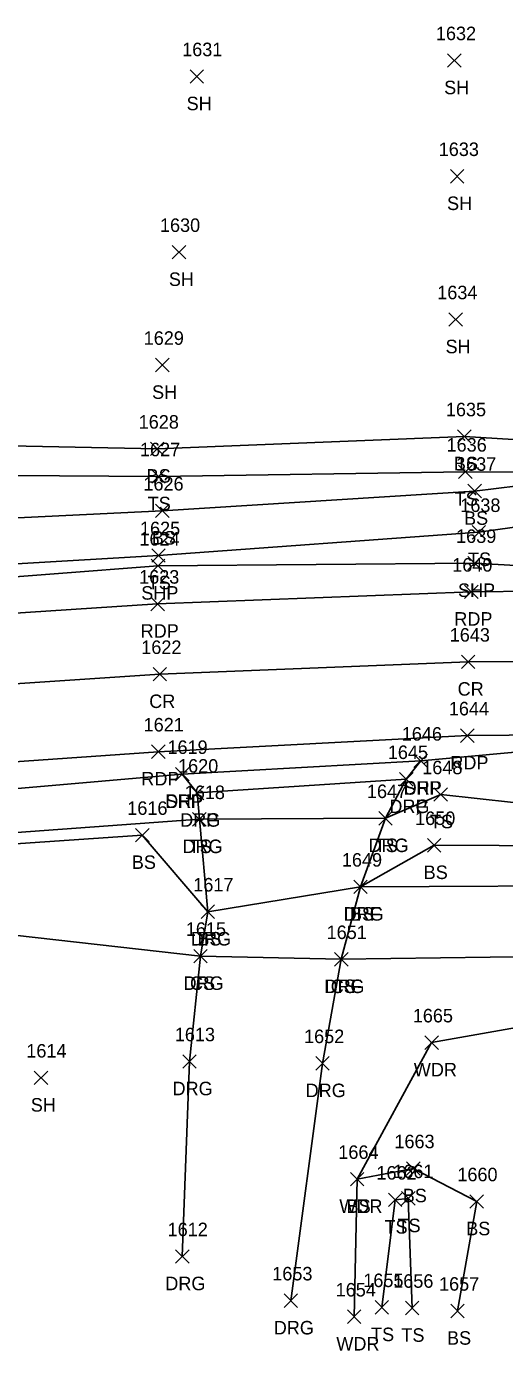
# Model space of a CAD drawing. Extents: x 1497084 to 1499861, y 734741 to 735567.
# Drawn here: x 1499358.9 to 1499429.7, y 735363.4 to 735559.4 of the extents above; entities that cross this region are included whole.
import ezdxf

# ---------------------------------------------------------------- set-up
doc = ezdxf.new("R2010")
doc.units = 0
for name, color, linetype in [('L_A', 7, 'Continuous'), ('L_I', 7, 'Continuous'), ('L_TIC', 7, 'Continuous'), ('LAWA', 7, 'Continuous'), ('LELB', 7, 'Continuous'), ('P_A', 7, 'Continuous'), ('P_I', 7, 'Continuous'), ('P_TIC', 7, 'Continuous'), ('PET', 7, 'Continuous'), ('PRC', 7, 'Continuous'), ('PSP', 7, 'Continuous'), ('R_A', 7, 'Continuous'), ('R_I', 7, 'Continuous'), ('R_TIC', 7, 'Continuous'), ('RDF', 7, 'Continuous'), ('RDG', 7, 'Continuous'), ('RDP', 7, 'Continuous')]:
    doc.layers.add(name, color=color, linetype=linetype)

msp = doc.modelspace()

# ---------------------------------------------------------------- linework, layer by layer
at = {"layer": 'L_TIC'}
for points in [[(1499421.24, 735553.38), (1499423.24, 735555.38)], [(1499423.24, 735553.38), (1499421.24, 735555.38)], [(1499383.1, 735551.01), (1499385.1, 735553.01)], [(1499385.1, 735551.01), (1499383.1, 735553.01)], [(1499421.66, 735536.23), (1499423.66, 735538.23)], [(1499423.66, 735536.23), (1499421.66, 735538.23)], [(1499380.47, 735524.99), (1499382.47, 735526.99)], [(1499382.47, 735524.99), (1499380.47, 735526.99)], [(1499421.44, 735515.03), (1499423.44, 735517.03)], [(1499423.44, 735515.03), (1499421.44, 735517.03)], [(1499377.98, 735508.28), (1499379.98, 735510.28)], [(1499379.98, 735508.28), (1499377.98, 735510.28)], [(1499422.72, 735497.7), (1499424.72, 735499.7)], [(1499424.72, 735497.7), (1499422.72, 735499.7)], [(1499377.23, 735495.87), (1499379.23, 735497.87)], [(1499379.23, 735495.87), (1499377.23, 735497.87)], [(1499377.42, 735491.78), (1499379.42, 735493.78)], [(1499379.42, 735491.78), (1499377.42, 735493.78)], [(1499422.87, 735492.47), (1499424.87, 735494.47)], [(1499424.87, 735492.47), (1499422.87, 735494.47)], [(1499424.23, 735489.63), (1499426.23, 735491.63)], [(1499426.23, 735489.63), (1499424.23, 735491.63)], [(1499377.98, 735486.71), (1499379.98, 735488.71)], [(1499379.98, 735486.71), (1499377.98, 735488.71)], [(1499424.85, 735483.53), (1499426.85, 735485.53)], [(1499426.85, 735483.53), (1499424.85, 735485.53)], [(1499377.42, 735480.09), (1499379.42, 735482.09)], [(1499379.42, 735480.09), (1499377.42, 735482.09)], [(1499419.22, 735444.71), (1499421.22, 735446.71)], [(1499421.22, 735444.71), (1499419.22, 735446.71)], [(1499383.48, 735441.03), (1499385.48, 735443.03)], [(1499385.48, 735441.03), (1499383.48, 735443.03)], [(1499411.03, 735441.18), (1499413.03, 735443.18)], [(1499413.03, 735441.18), (1499411.03, 735443.18)], [(1499375.02, 735438.69), (1499377.02, 735440.69)], [(1499377.02, 735438.69), (1499375.02, 735440.69)], [(1499418.24, 735437.19), (1499420.24, 735439.19)], [(1499420.24, 735437.19), (1499418.24, 735439.19)], [(1499407.33, 735431.03), (1499409.33, 735433.03)], [(1499409.33, 735431.03), (1499407.33, 735433.03)], [(1499384.74, 735427.35), (1499386.74, 735429.35)], [(1499386.74, 735427.35), (1499384.74, 735429.35)], [(1499383.64, 735420.78), (1499385.64, 735422.78)], [(1499385.64, 735420.78), (1499383.64, 735422.78)], [(1499404.49, 735420.31), (1499406.49, 735422.31)], [(1499406.49, 735420.31), (1499404.49, 735422.31)], [(1499417.87, 735407.97), (1499419.87, 735409.97)], [(1499419.87, 735407.97), (1499417.87, 735409.97)], [(1499360.03, 735402.76), (1499362.03, 735404.76)], [(1499362.03, 735402.76), (1499360.03, 735404.76)], [(1499415.15, 735389.34), (1499417.15, 735391.34)], [(1499417.15, 735389.34), (1499415.15, 735391.34)], [(1499406.84, 735387.76), (1499408.84, 735389.76)], [(1499408.84, 735387.76), (1499406.84, 735389.76)], [(1499406.84, 735387.76), (1499408.84, 735389.76)], [(1499408.84, 735387.76), (1499406.84, 735389.76)], [(1499412.48, 735384.7), (1499414.48, 735386.7)], [(1499414.48, 735384.7), (1499412.48, 735386.7)], [(1499412.48, 735384.7), (1499414.48, 735386.7)], [(1499414.48, 735384.7), (1499412.48, 735386.7)], [(1499414.41, 735384.91), (1499416.41, 735386.91)], [(1499416.41, 735384.91), (1499414.41, 735386.91)], [(1499424.55, 735384.45), (1499426.55, 735386.45)], [(1499426.55, 735384.45), (1499424.55, 735386.45)], [(1499410.49, 735368.78), (1499412.49, 735370.78)], [(1499412.49, 735368.78), (1499410.49, 735370.78)], [(1499414.98, 735368.68), (1499416.98, 735370.68)], [(1499416.98, 735368.68), (1499414.98, 735370.68)], [(1499421.71, 735368.25), (1499423.71, 735370.25)], [(1499423.71, 735368.25), (1499421.71, 735370.25)], [(1499406.4, 735367.39), (1499408.4, 735369.39)], [(1499408.4, 735367.39), (1499406.4, 735369.39)]]:
    msp.add_lwpolyline(points, dxfattribs=at)
at = {"layer": 'LAWA'}
msp.add_lwpolyline([(1499407.4, 735368.39), (1499407.84, 735388.76), (1499418.87, 735408.97), (1499449.6, 735414.41), (1499467.22, 735411), (1499485.54, 735404.01), (1499495.84, 735403.46), (1499517.61, 735404.27)], dxfattribs=at)
at = {"layer": 'LELB'}
for points in [[(1498873.92, 735413.56), (1498885.61, 735419.45), (1498937.6, 735431.47), (1498992.42, 735446.17), (1499046.55, 735456.42), (1499100.05, 735466.4), (1499155.3, 735475.02), (1499211.81, 735485.81), (1499272.89, 735498.35), (1499312.63, 735498.22), (1499378.23, 735496.87), (1499423.72, 735498.7), (1499448.77, 735497.16), (1499468.03, 735503.5), (1499479.61, 735506.38), (1499485.8, 735535.79), (1499495.73, 735555.05)], [(1498887.06, 735413.08), (1498886.64, 735416.64), (1498937.22, 735426.43), (1498992.82, 735439.97), (1499047, 735450.43), (1499100.75, 735458.28), (1499155.76, 735466.18), (1499214.75, 735478.18), (1499272.85, 735494.27), (1499312.36, 735493.24), (1499378.42, 735492.78), (1499423.87, 735493.47), (1499447.7, 735493.36), (1499467.98, 735499.39), (1499480.88, 735502.15), (1499491.75, 735532.72), (1499501.47, 735549.91)], [(1499315.72, 735484.63), (1499378.98, 735487.71), (1499425.23, 735490.63), (1499447.7, 735493.36), (1499468.5, 735489.63), (1499492.74, 735487.59), (1499503.65, 735483.67), (1499512.79, 735485.66), (1499516.41, 735481.94), (1499515.9, 735479.25)], [(1498836.02, 735409.82), (1498851.62, 735410.69), (1498873.71, 735408.53), (1498887.41, 735411.13), (1498937.88, 735419.58), (1498994.04, 735428.91), (1499054.48, 735438.88), (1499102.91, 735446.6), (1499157.52, 735455.49), (1499217.09, 735464.03), (1499265.79, 735469.16), (1499273.78, 735473.78), (1499316.12, 735477.44), (1499378.42, 735481.09), (1499425.85, 735484.53), (1499445.24, 735487.28), (1499459.87, 735483.77), (1499494.5, 735481.39), (1499511.88, 735480.66), (1499514.4, 735477.39)], [(1498902.07, 735368.05), (1498907.17, 735371.51), (1498940.32, 735377.55), (1498999.63, 735387.02), (1499017.69, 735389.23), (1499022.6, 735383.12), (1499048.5, 735392.29), (1499056.36, 735395.92), (1499109.05, 735409.57), (1499159.67, 735419.26), (1499225.84, 735428.89), (1499272.31, 735428.88), (1499323.36, 735436.06), (1499376.02, 735439.69), (1499385.74, 735428.35), (1499408.33, 735432.03), (1499419.24, 735438.19), (1499448.18, 735438.04), (1499493.15, 735436.77), (1499505.9, 735439.37), (1499516.74, 735441.77), (1499516.38, 735446.4), (1499513.83, 735450.64)], [(1499224.87, 735431.1), (1499271.08, 735434.05), (1499322.87, 735437.57), (1499384.48, 735442.03), (1499412.03, 735442.18), (1499420.22, 735445.71), (1499447.12, 735442.74), (1499493.29, 735444.7), (1499504.12, 735447.13), (1499512.27, 735451.02)], [(1499047.27, 735383.52), (1499066.78, 735390.4), (1499110.69, 735404.23), (1499164.91, 735411.78), (1499229.89, 735424.14), (1499272.31, 735428.88), (1499323.85, 735428.64), (1499384.64, 735421.78), (1499405.49, 735421.31)], [(1499422.71, 735369.25), (1499425.55, 735385.45), (1499416.15, 735390.34), (1499407.84, 735388.76)], [(1499411.49, 735369.78), (1499413.48, 735385.7)], [(1499415.98, 735369.68), (1499415.41, 735385.91), (1499413.48, 735385.7)]]:
    msp.add_lwpolyline(points, dxfattribs=at)
at = {"layer": 'P_TIC'}
for points in [[(1499377.34, 735478.55), (1499379.34, 735480.55)], [(1499379.34, 735478.55), (1499377.34, 735480.55)], [(1499424.23, 735478.95), (1499426.23, 735480.95)], [(1499426.23, 735478.95), (1499424.23, 735480.95)], [(1499423.75, 735474.7), (1499425.75, 735476.7)], [(1499425.75, 735474.7), (1499423.75, 735476.7)], [(1499377.29, 735472.92), (1499379.29, 735474.92)], [(1499379.29, 735472.92), (1499377.29, 735474.92)], [(1499423.29, 735464.34), (1499425.29, 735466.34)], [(1499425.29, 735464.34), (1499423.29, 735466.34)], [(1499377.61, 735462.51), (1499379.61, 735464.51)], [(1499379.61, 735462.51), (1499377.61, 735464.51)], [(1499423.16, 735453.42), (1499425.16, 735455.42)], [(1499425.16, 735453.42), (1499423.16, 735455.42)], [(1499377.39, 735451.04), (1499379.39, 735453.04)], [(1499379.39, 735451.04), (1499377.39, 735453.04)], [(1499416.25, 735449.68), (1499418.25, 735451.68)], [(1499418.25, 735449.68), (1499416.25, 735451.68)], [(1499380.94, 735447.71), (1499382.94, 735449.71)], [(1499382.94, 735447.71), (1499380.94, 735449.71)]]:
    msp.add_lwpolyline(points, dxfattribs=at)
at = {"layer": 'PET'}
for points in [[(1498838.32, 735395.91), (1498888.99, 735404.3), (1498938.22, 735411.59), (1498994.69, 735421.68), (1499054.78, 735430.96), (1499104.38, 735439.6), (1499157.66, 735447.8), (1499219.31, 735457.47), (1499265.92, 735463.89), (1499317.31, 735469.95), (1499378.29, 735473.92), (1499424.75, 735475.7), (1499462.5, 735476.09), (1499495.09, 735475.96), (1499513.91, 735475.18)], [(1498842.44, 735373.21), (1498892.67, 735381.87), (1498940.26, 735389.17), (1498997.67, 735398.94), (1499056.44, 735408.41), (1499108.2, 735417.59), (1499160.18, 735425.34), (1499224.61, 735435.78), (1499269.11, 735441.52), (1499319.5, 735447.91), (1499378.39, 735452.04), (1499424.16, 735454.42), (1499461.26, 735454.74), (1499493.51, 735454.63), (1499512.44, 735453.4), (1499513.2, 735464.25), (1499513.91, 735475.18)]]:
    msp.add_lwpolyline(points, dxfattribs=at)
at = {"layer": 'PRC'}
msp.add_lwpolyline([(1498839.89, 735384.37), (1498890.74, 735392.79), (1498939.31, 735400.24), (1498995.85, 735410.01), (1499056.08, 735419.64), (1499106.34, 735428.63), (1499159.02, 735436.58), (1499221.74, 735447.44), (1499267.15, 735453.23), (1499318.55, 735459.5), (1499378.61, 735463.51), (1499424.29, 735465.34), (1499461.73, 735465.4), (1499494.05, 735465.28), (1499513.2, 735464.25)], dxfattribs=at)
at = {"layer": 'PSP'}
for points in [[(1498833.8, 735399.85), (1498855.6, 735403.69), (1498873.7, 735405.84), (1498888.17, 735408.98), (1498937.73, 735416.37), (1498993.87, 735425.67), (1499054.79, 735435.66), (1499103.37, 735443.86), (1499157.46, 735452.91), (1499218.03, 735462.22), (1499265.79, 735469.16), (1499316.87, 735474.83), (1499378.34, 735479.55), (1499425.23, 735479.95), (1499462.88, 735477.81), (1499495.09, 735475.96)], [(1498843.61, 735368.57), (1498860.46, 735371.23), (1498865.28, 735372.42), (1498905.37, 735378.8), (1498940.19, 735384.06), (1498998.48, 735394.31), (1499018.85, 735397.58), (1499054.41, 735403.83), (1499108.72, 735412.03), (1499160.14, 735420.81), (1499224.87, 735431.1), (1499270.68, 735437.25), (1499320.13, 735443.34), (1499381.94, 735448.71), (1499417.25, 735450.68), (1499461.26, 735454.74)]]:
    msp.add_lwpolyline(points, dxfattribs=at)
at = {"layer": 'R_TIC'}
for points in [[(1499416.25, 735449.68), (1499418.25, 735451.68)], [(1499418.25, 735449.68), (1499416.25, 735451.68)], [(1499380.94, 735447.71), (1499382.94, 735449.71)], [(1499382.94, 735447.71), (1499380.94, 735449.71)], [(1499414.12, 735446.96), (1499416.12, 735448.96)], [(1499416.12, 735446.96), (1499414.12, 735448.96)], [(1499414.12, 735446.96), (1499416.12, 735448.96)], [(1499416.12, 735446.96), (1499414.12, 735448.96)], [(1499383.15, 735444.94), (1499385.15, 735446.94)], [(1499385.15, 735444.94), (1499383.15, 735446.94)], [(1499383.15, 735444.94), (1499385.15, 735446.94)], [(1499385.15, 735444.94), (1499383.15, 735446.94)], [(1499383.48, 735441.03), (1499385.48, 735443.03)], [(1499385.48, 735441.03), (1499383.48, 735443.03)], [(1499411.03, 735441.18), (1499413.03, 735443.18)], [(1499413.03, 735441.18), (1499411.03, 735443.18)], [(1499407.33, 735431.03), (1499409.33, 735433.03)], [(1499409.33, 735431.03), (1499407.33, 735433.03)], [(1499407.33, 735431.03), (1499409.33, 735433.03)], [(1499409.33, 735431.03), (1499407.33, 735433.03)], [(1499384.74, 735427.35), (1499386.74, 735429.35)], [(1499386.74, 735427.35), (1499384.74, 735429.35)], [(1499383.64, 735420.78), (1499385.64, 735422.78)], [(1499385.64, 735420.78), (1499383.64, 735422.78)], [(1499404.49, 735420.31), (1499406.49, 735422.31)], [(1499406.49, 735420.31), (1499404.49, 735422.31)], [(1499404.49, 735420.31), (1499406.49, 735422.31)], [(1499406.49, 735420.31), (1499404.49, 735422.31)], [(1499382.01, 735405.18), (1499384.01, 735407.18)], [(1499384.01, 735405.18), (1499382.01, 735407.18)], [(1499401.72, 735404.9), (1499403.72, 735406.9)], [(1499403.72, 735404.9), (1499401.72, 735406.9)], [(1499380.94, 735376.32), (1499382.94, 735378.32)], [(1499382.94, 735376.32), (1499380.94, 735378.32)], [(1499397.01, 735369.77), (1499399.01, 735371.77)], [(1499399.01, 735369.77), (1499397.01, 735371.77)]]:
    msp.add_lwpolyline(points, dxfattribs=at)
at = {"layer": 'RDF'}
for points in [[(1499408.33, 735432.03), (1499449.04, 735432.22), (1499492.72, 735433.69), (1499504.93, 735435.39), (1499516.71, 735431.72)], [(1499405.49, 735421.31), (1499449.6, 735421.9), (1499483.66, 735418.66), (1499504.7, 735422.91), (1499516.71, 735431.72)]]:
    msp.add_lwpolyline(points, dxfattribs=at)
at = {"layer": 'RDG'}
for points in [[(1499415.12, 735447.96), (1499412.03, 735442.18), (1499408.33, 735432.03), (1499405.49, 735421.31), (1499402.72, 735405.9), (1499398.01, 735370.77)], [(1499381.94, 735377.32), (1499383.01, 735406.18), (1499384.64, 735421.78), (1499385.74, 735428.35), (1499384.48, 735442.03), (1499384.15, 735445.94)]]:
    msp.add_lwpolyline(points, dxfattribs=at)
at = {"layer": 'RDP'}
msp.add_lwpolyline([(1499381.94, 735448.71), (1499384.15, 735445.94), (1499415.12, 735447.96), (1499417.25, 735450.68)], dxfattribs=at)

# ---------------------------------------------------------------- texts
at = {"layer": 'L_A'}
for s, p in [('SH', (1499420.72, 735549.38)), ('SH', (1499382.59, 735547.01)), ('SH', (1499421.15, 735532.23)), ('SH', (1499379.96, 735520.99)), ('SH', (1499420.93, 735511.03)), ('SH', (1499377.47, 735504.28)), ('BS', (1499422.16, 735493.7)), ('BS', (1499376.67, 735491.87)), ('TS', (1499376.82, 735487.78)), ('TS', (1499422.28, 735488.47)), ('BS', (1499423.67, 735485.63)), ('BS', (1499377.42, 735482.71)), ('TS', (1499424.26, 735479.53)), ('TS', (1499376.83, 735476.09)), ('TS', (1499418.63, 735440.71)), ('TS', (1499382.89, 735437.03)), ('TS', (1499410.44, 735437.18)), ('BS', (1499374.47, 735434.69)), ('BS', (1499417.69, 735433.19)), ('BS', (1499406.77, 735427.03)), ('BS', (1499384.18, 735423.35)), ('CS', (1499383.08, 735416.78)), ('CS', (1499403.93, 735416.31)), ('WDR', (1499416.23, 735403.97)), ('SH', (1499359.51, 735398.76)), ('BS', (1499414.59, 735385.34)), ('WDR', (1499405.2, 735383.76)), ('BS', (1499406.28, 735383.76)), ('TS', (1499411.89, 735380.7)), ('TS', (1499411.89, 735380.7)), ('TS', (1499413.82, 735380.91)), ('BS', (1499423.99, 735380.45)), ('TS', (1499409.9, 735364.78)), ('TS', (1499414.39, 735364.68)), ('BS', (1499421.15, 735364.25)), ('WDR', (1499404.76, 735363.39))]:
    msp.add_text(s, height=2, dxfattribs=at).set_placement(p)
at = {"layer": 'L_I'}
for s, p in [('1632', (1499419.5, 735557.38)), ('1631', (1499381.93, 735555.01)), ('1633', (1499419.92, 735540.23)), ('1630', (1499378.64, 735528.99)), ('1634', (1499419.7, 735519.03)), ('1629', (1499376.23, 735512.28)), ('1635', (1499420.98, 735501.7)), ('1628', (1499375.49, 735499.87)), ('1627', (1499375.68, 735495.78)), ('1636', (1499421.08, 735496.47)), ('1637', (1499422.49, 735493.63)), ('1626', (1499376.19, 735490.71)), ('1638', (1499423.11, 735487.53)), ('1625', (1499375.68, 735484.09)), ('1648', (1499417.48, 735448.71)), ('1618', (1499382.31, 735445.03)), ('1647', (1499409.29, 735445.18)), ('1616', (1499373.8, 735442.69)), ('1650', (1499416.42, 735441.19)), ('1649', (1499405.58, 735435.03)), ('1617', (1499383.57, 735431.35)), ('1615', (1499382.47, 735424.78)), ('1651', (1499403.32, 735424.31)), ('1665', (1499416.08, 735411.97)), ('1614', (1499358.85, 735406.76)), ('1663', (1499413.36, 735393.34)), ('1664', (1499405.05, 735391.76)), ('1664', (1499405.05, 735391.76)), ('1662', (1499410.69, 735388.7)), ('1662', (1499410.69, 735388.7)), ('1661', (1499413.19, 735388.91)), ('1660', (1499422.68, 735388.45)), ('1654', (1499404.66, 735371.39)), ('1655', (1499408.75, 735372.78)), ('1656', (1499413.18, 735372.68)), ('1657', (1499419.97, 735372.25))]:
    msp.add_text(s, height=2, dxfattribs=at).set_placement(p)
at = {"layer": 'P_A'}
for s, p in [('SHP', (1499375.87, 735474.55)), ('SHP', (1499422.77, 735474.95)), ('RDP', (1499422.23, 735470.7)), ('RDP', (1499375.78, 735468.92)), ('CR', (1499422.72, 735460.34)), ('CR', (1499377.05, 735458.51)), ('RDP', (1499421.64, 735449.42)), ('RDP', (1499375.88, 735447.04)), ('SHP', (1499414.78, 735445.68)), ('SHP', (1499379.47, 735443.71))]:
    msp.add_text(s, height=2, dxfattribs=at).set_placement(p)
at = {"layer": 'P_I'}
for s, p in [('1624', (1499375.6, 735482.55)), ('1639', (1499422.49, 735482.95)), ('1640', (1499421.92, 735478.7)), ('1623', (1499375.55, 735476.92)), ('1643', (1499421.55, 735468.34)), ('1622', (1499375.87, 735466.51)), ('1644', (1499421.42, 735457.42)), ('1621', (1499376.22, 735455.04)), ('1646', (1499414.45, 735453.68)), ('1619', (1499379.75, 735451.71))]:
    msp.add_text(s, height=2, dxfattribs=at).set_placement(p)
at = {"layer": 'R_A'}
for s, p in [('DRP', (1499414.73, 735445.68)), ('DRP', (1499379.42, 735443.71)), ('DRG', (1499412.61, 735442.96)), ('DRP', (1499412.61, 735442.96)), ('DRG', (1499381.63, 735440.94)), ('DRP', (1499381.63, 735440.94)), ('DRG', (1499381.97, 735437.03)), ('DRG', (1499409.52, 735437.18)), ('DRG', (1499405.82, 735427.03)), ('DRF', (1499405.86, 735427.03)), ('DRG', (1499383.23, 735423.35)), ('DRG', (1499382.13, 735416.78)), ('DRG', (1499402.98, 735416.31)), ('DRF', (1499403.03, 735416.31)), ('DRG', (1499380.5, 735401.18)), ('DRG', (1499400.21, 735400.9)), ('DRG', (1499379.43, 735372.32)), ('DRG', (1499395.49, 735365.77))]:
    msp.add_text(s, height=2, dxfattribs=at).set_placement(p)
at = {"layer": 'R_I'}
for s, p in [('1646', (1499414.45, 735453.68)), ('1619', (1499379.75, 735451.71)), ('1645', (1499412.38, 735450.96)), ('1645', (1499412.38, 735450.96)), ('1620', (1499381.32, 735448.94)), ('1620', (1499381.32, 735448.94)), ('1618', (1499382.31, 735445.03)), ('1647', (1499409.29, 735445.18)), ('1649', (1499405.58, 735435.03)), ('1649', (1499405.58, 735435.03)), ('1617', (1499383.57, 735431.35)), ('1615', (1499382.47, 735424.78)), ('1651', (1499403.32, 735424.31)), ('1651', (1499403.32, 735424.31)), ('1613', (1499380.84, 735409.18)), ('1652', (1499399.98, 735408.9)), ('1612', (1499379.77, 735380.32)), ('1653', (1499395.27, 735373.77))]:
    msp.add_text(s, height=2, dxfattribs=at).set_placement(p)

doc.saveas('drawing.dxf')
